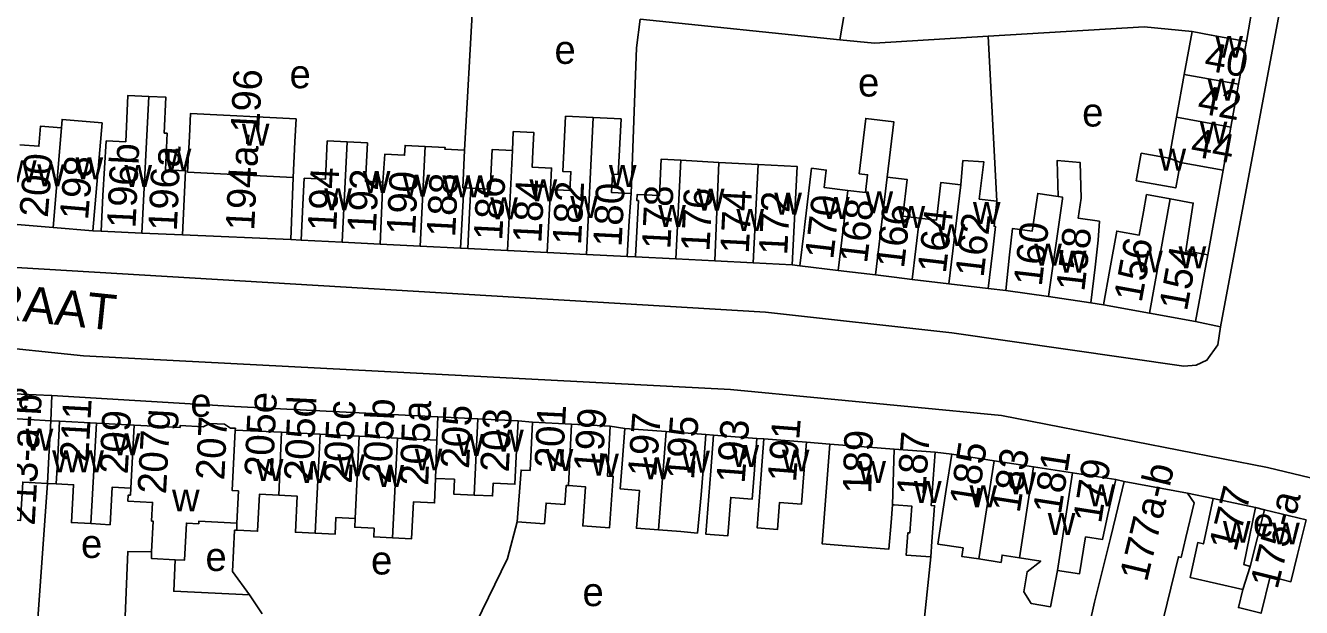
# Model space of a CAD drawing. Extents: x 157569 to 159501, y 382907 to 384670.
# Drawn here: x 158378.5 to 158557, y 383135.7 to 383217.2 of the extents above; entities that cross this region are included whole.
import ezdxf

# ---------------------------------------------------------------- set-up
doc = ezdxf.new("R2010")
doc.units = 0
for name, color, linetype in [('BLT_Basislijn', 7, 'Continuous'), ('BLT_Bebouwing', 7, 'Continuous'), ('BLT_Centroide', 7, 'Continuous'), ('BLT_Huisnummer', 7, 'Continuous'), ('BLT_Huisnummer_ tussenligend', 7, 'Continuous'), ('BLT_Huisnummer_reeks', 7, 'Continuous'), ('BLT_Onderdoorgang_en_onderverdeling', 7, 'Continuous'), ('BLT_Onderverdeling_panden', 7, 'Continuous'), ('BLT_Straatnaam', 7, 'Continuous')]:
    doc.layers.add(name, color=color, linetype=linetype)

msp = doc.modelspace()

# ---------------------------------------------------------------- linework, layer by layer
at = {"layer": 'BLT_Basislijn'}
for p, q in [((158494.57, 383228.1), (158492.39, 383215.18)), ((158550.98, 383224.75), (158549.26, 383214.95)), ((158441.03, 383220.43), (158439.9, 383199.74)), ((158492.39, 383215.18), (158464.44, 383218.06)), ((158514.36, 383192.58), (158513.12, 383215.69)), ((158415.92, 383195.91), (158415.58, 383187.21)), ((158543.84, 383185.09), (158545.99, 383196.95)), ((158387.91, 383188.45), (158389.06, 383188.4)), ((158400.44, 383187.87), (158415.58, 383187.21)), ((158415.58, 383187.21), (158417.03, 383187.16)), ((158463.81, 383184.79), (158462.66, 383184.84)), ((158485.73, 383183.68), (158486.81, 383183.53)), ((158515.6, 383180.1), (158513.12, 383180.39)), ((158529.25, 383178.1), (158527.51, 383178.38)), ((158545.62, 383175.03), (158542.14, 383175.76)), ((158382.03, 383161.87), (158382.17, 383165.41)), ((158447.38, 383161.85), (158449.4, 383161.66)), ((158460.28, 383161.11), (158462.32, 383160.8)), ((158474.72, 383159.84), (158473.63, 383159.94)), ((158480.78, 383159.38), (158481.77, 383159.32)), ((158491, 383158.6), (158487.7, 383158.86)), ((158505.73, 383157.49), (158508.04, 383157.18)), ((158380.05, 383132.21), (158381.55, 383153.1)), ((158532.17, 383153.37), (158531, 383153.63)), ((158544.6, 383150.99), (158541.02, 383151.73)), ((158550.55, 383149.72), (158551.78, 383149.4)), ((158407.45, 383140.78), (158407.72, 383146.55)), ((158407.72, 383146.55), (158408.05, 383146.54)), ((158505.11, 383142.8), (158503.88, 383130.9)), ((158407.45, 383140.78), (158409.81, 383137.51))]:
    msp.add_line(p, q, dxfattribs=at)
for points in [[(158555.85, 383237.47), (158556.46, 383236.09), (158556.55, 383234.91), (158556.23, 383231.55), (158545.62, 383175.03)], [(158135.77, 383231.67), (158137.79, 383229.1), (158140.67, 383227.08), (158144.24, 383226.07), (158171.27, 383222.4), (158308.16, 383193.45), (158320.58, 383190.57), (158326.95, 383189.46), (158362.07, 383184.81), (158374.02, 383183.51), (158481.99, 383177.07), (158508.03, 383174.16), (158540.49, 383169.52), (158542.23, 383169.64), (158543.74, 383170.33), (158545.24, 383172.5), (158545.62, 383175.03)], [(158464.44, 383218.06), (158463.94, 383214.05), (158463.22, 383193.67)], [(158492.39, 383215.18), (158497.23, 383214.73), (158513.12, 383215.69)], [(158541.66, 383216.34), (158534.94, 383217), (158513.12, 383215.69)], [(158136.23, 383207.98), (158138.34, 383210.7), (158142.33, 383213.13), (158148.56, 383213.38), (158153.24, 383212.69), (158183.67, 383207.66), (158286.08, 383185.1), (158316.24, 383179.46), (158331.59, 383176.95), (158343.62, 383175.44), (158386.57, 383170.97), (158477.11, 383166.26), (158514.99, 383162.58), (158552.21, 383155.31), (158614.72, 383140.3), (158637.24, 383136.07), (158653.85, 383134.55), (158675.54, 383133.02), (158693.44, 383133.82), (158697.11, 383133.9), (158699.66, 383132.24), (158700.59, 383130.97), (158702.07, 383127.4)], [(158371.53, 383165.87), (158382.06, 383165.41), (158382.17, 383165.41)], [(158436.17, 383162.41), (158407.73, 383163.87), (158382.17, 383165.41)], [(158439.7, 383129.86), (158445.88, 383142.61), (158447.26, 383147.72)]]:
    msp.add_lwpolyline(points, dxfattribs=at)
at = {"layer": 'BLT_Bebouwing'}
for p, q in [((158540.57, 383210.34), (158541.66, 383216.34)), ((158549.26, 383214.95), (158548.17, 383208.95)), ((158539.48, 383204.34), (158540.57, 383210.34)), ((158548.17, 383208.95), (158547.08, 383202.95)), ((158538.43, 383198.6), (158539.48, 383204.34)), ((158547.08, 383202.95), (158545.99, 383196.95)), ((158470.16, 383198.34), (158475.47, 383198.03)), ((158475.47, 383198.03), (158480.96, 383197.72)), ((158545.99, 383196.95), (158540.03, 383198.03)), ((158439.77, 383194.47), (158440.77, 383194.42)), ((158382.33, 383188.92), (158376.76, 383189.39)), ((158387.91, 383188.45), (158382.33, 383188.92)), ((158389.06, 383188.4), (158394.75, 383188.14)), ((158400.44, 383187.87), (158394.75, 383188.14)), ((158422.78, 383186.86), (158417.03, 383187.16)), ((158428.09, 383186.6), (158422.78, 383186.86)), ((158433.67, 383186.31), (158428.09, 383186.6)), ((158439.34, 383186.03), (158433.67, 383186.31)), ((158439.34, 383186.03), (158440.34, 383185.98)), ((158445.9, 383185.69), (158440.34, 383185.98)), ((158451.47, 383185.41), (158445.9, 383185.69)), ((158456.93, 383185.13), (158451.47, 383185.41)), ((158462.66, 383184.84), (158456.93, 383185.13)), ((158463.81, 383184.79), (158469.46, 383184.51)), ((158469.46, 383184.51), (158474.88, 383184.23)), ((158474.88, 383184.23), (158480.26, 383183.96)), ((158480.26, 383183.96), (158485.73, 383183.68)), ((158492.16, 383182.89), (158486.81, 383183.53)), ((158543.84, 383185.09), (158542.14, 383175.76)), ((158497.37, 383182.27), (158492.16, 383182.89)), ((158502.52, 383181.65), (158507.65, 383181.04)), ((158507.65, 383181.04), (158513.12, 383180.39)), ((158521.55, 383179.24), (158515.6, 383180.1)), ((158527.51, 383178.38), (158521.55, 383179.24)), ((158535.69, 383176.93), (158529.25, 383178.1)), ((158542.14, 383175.76), (158535.69, 383176.93)), ((158382.03, 383161.87), (158375.76, 383162.22)), ((158436.17, 383162.41), (158436.01, 383159.17)), ((158441.77, 383162.13), (158436.17, 383162.41)), ((158447.38, 383161.85), (158441.77, 383162.13)), ((158382.03, 383161.87), (158383.25, 383161.8)), ((158388.39, 383161.54), (158383.25, 383161.8)), ((158393.7, 383161.27), (158388.39, 383161.54)), ((158414.28, 383160.25), (158407.81, 383160.57)), ((158419.71, 383159.98), (158414.28, 383160.25)), ((158454.84, 383161.39), (158449.4, 383161.66)), ((158460.28, 383161.11), (158454.84, 383161.39)), ((158468.09, 383160.36), (158462.32, 383160.8)), ((158473.63, 383159.94), (158468.09, 383160.36)), ((158425.17, 383159.71), (158419.71, 383159.98)), ((158430.53, 383159.44), (158425.17, 383159.71)), ((158436.01, 383159.17), (158430.53, 383159.44)), ((158480.78, 383159.38), (158474.72, 383159.84)), ((158487.7, 383158.86), (158481.77, 383159.32)), ((158500, 383157.91), (158491, 383158.6)), ((158505.73, 383157.49), (158500, 383157.91)), ((158513.97, 383156.26), (158508.04, 383157.18)), ((158519.49, 383155.41), (158513.97, 383156.26)), ((158524.95, 383154.57), (158519.49, 383155.41)), ((158382.77, 383153.03), (158381.55, 383153.1)), ((158531, 383153.63), (158524.95, 383154.57)), ((158541.02, 383151.73), (158532.17, 383153.37)), ((158544.6, 383150.99), (158550.55, 383149.72)), ((158549.78, 383141.46), (158551.78, 383149.4)), ((158551.78, 383149.4), (158557.6, 383147.99)), ((158408.05, 383146.54), (158408.04, 383147.53)), ((158409.81, 383137.51), (158411.56, 383134.85))]:
    msp.add_line(p, q, dxfattribs=at)
for points in [[(158541.66, 383216.34), (158544.34, 383215.85), (158549.26, 383214.95)], [(158395.75, 383207.25), (158392.81, 383207.39), (158392.51, 383200.92), (158389.78, 383201.04), (158389.3, 383193.39), (158389.06, 383188.4)], [(158395.75, 383207.25), (158398.12, 383207.14), (158397.89, 383202.13), (158398.28, 383202.11), (158398.04, 383196.98), (158400.86, 383196.85), (158400.68, 383192.87), (158400.44, 383187.87)], [(158416.34, 383204.12), (158401.57, 383204.87), (158401.41, 383201.65), (158401.15, 383196.65)], [(158377.68, 383200.5), (158380.35, 383200.28), (158380.59, 383203.11), (158383.5, 383202.86)], [(158383.5, 383202.86), (158383.59, 383204.03), (158389.18, 383203.56), (158387.91, 383188.45)], [(158415.92, 383195.91), (158416.17, 383200.9), (158416.34, 383204.12)], [(158451.91, 383194.22), (158454.63, 383194.08), (158454.76, 383196.71), (158453.63, 383196.77), (158454.02, 383204.49), (158457.9, 383204.29)], [(158457.9, 383204.29), (158461.78, 383204.1), (158461.39, 383196.35), (158460.59, 383196.39), (158460.46, 383193.81), (158463.22, 383193.67)], [(158493.5, 383194.11), (158495.96, 383193.83), (158496.26, 383196.29), (158495.1, 383196.43), (158496.02, 383204.18), (158499.92, 383203.71), (158499, 383195.95)], [(158446.62, 383199.71), (158446.7, 383202.33), (158449.6, 383202.19), (158449.46, 383199.56), (158449.35, 383197.35), (158452.07, 383197.22), (158451.91, 383194.22)], [(158417.03, 383187.16), (158417.29, 383192.15), (158417.47, 383195.81), (158420.42, 383195.66), (158420.69, 383201.03), (158423.49, 383200.89)], [(158423.49, 383200.89), (158426.3, 383200.75), (158426.02, 383195.38), (158428.45, 383195.25)], [(158428.45, 383195.25), (158428.73, 383199.16), (158431.51, 383199.02), (158431.58, 383200.4), (158434.37, 383200.26)], [(158434.37, 383200.26), (158437.17, 383200.12), (158437.15, 383199.87), (158439.9, 383199.74)], [(158439.77, 383194.47), (158439.64, 383194.47), (158439.9, 383199.74)], [(158440.77, 383194.42), (158443.48, 383194.28), (158443.77, 383199.85), (158446.62, 383199.71)], [(158470.16, 383198.34), (158467.4, 383198.48), (158467.14, 383193.37), (158464.02, 383193.53), (158463.97, 383192.7), (158464.21, 383192.69), (158463.81, 383184.91), (158463.81, 383184.79)], [(158485.73, 383183.68), (158486.43, 383197.44), (158480.96, 383197.72)], [(158509.3, 383194.9), (158509.6, 383198.28), (158512.51, 383198.11), (158511.89, 383192.88), (158514.36, 383192.58)], [(158522.91, 383193.27), (158522.78, 383198.27), (158526.02, 383197.99), (158526.15, 383193.04), (158525.74, 383190.21), (158528.69, 383189.79), (158528.52, 383187.16), (158528.08, 383183.35), (158527.51, 383178.38)], [(158538.43, 383198.6), (158534.54, 383199.31), (158533.84, 383195.45), (158539.38, 383194.45), (158540.03, 383198.03)], [(158401.15, 383196.65), (158415.92, 383195.91)], [(158486.81, 383183.53), (158487.4, 383188.49), (158487.46, 383188.96), (158488.44, 383197.2), (158490.48, 383196.95), (158490.19, 383194.51), (158493.5, 383194.11)], [(158499, 383195.95), (158501.8, 383195.64), (158501.19, 383190.5), (158503.54, 383190.22)], [(158503.54, 383190.22), (158505.89, 383189.94), (158506.52, 383195.23), (158509.3, 383194.9)], [(158463.22, 383193.67), (158462.92, 383189.84), (158462.66, 383184.84)], [(158513.12, 383180.39), (158513.72, 383185.35), (158514.16, 383189.05), (158513.95, 383189.08), (158514.36, 383192.58)], [(158515.6, 383180.1), (158516.14, 383185.07), (158516.54, 383188.79), (158519.3, 383188.4), (158520.06, 383193.68), (158522.91, 383193.27)], [(158529.25, 383178.1), (158530.14, 383183.02), (158531.13, 383188.42), (158534.26, 383187.86), (158534.85, 383191.1), (158535.29, 383193.51), (158538.6, 383192.91)], [(158538.6, 383192.91), (158541.81, 383192.33), (158540.78, 383185.64), (158543.84, 383185.09)], [(158502.52, 383181.65), (158500, 383181.95), (158497.37, 383182.27)], [(158407.81, 383160.57), (158407.83, 383160.82), (158407.14, 383160.85), (158406.32, 383161.39), (158404.28, 383161.5), (158403.33, 383161.02), (158400.1, 383161.2), (158400.09, 383160.94), (158393.7, 383161.27)], [(158447.38, 383161.85), (158447.13, 383156.85), (158446.93, 383152.99), (158443.9, 383153.14), (158443.81, 383151.34), (158441.24, 383151.46)], [(158449.4, 383161.66), (158449.06, 383154.91), (158447.8, 383154.97), (158447.26, 383147.72)], [(158460.28, 383161.11), (158459.9, 383154.11), (158460.69, 383154.07), (158460.15, 383146.87), (158456.42, 383147.14), (158456.82, 383152.61), (158454.41, 383152.79)], [(158462.32, 383160.8), (158461.94, 383155.82), (158461.68, 383152.33), (158464.35, 383152.12), (158463.94, 383146.83), (158467.04, 383146.6)], [(158473.63, 383159.94), (158473.25, 383154.96), (158472.99, 383151.48), (158472.46, 383146.14), (158470.13, 383146.36), (158467.04, 383146.6)], [(158474.72, 383159.84), (158474.34, 383154.85), (158473.66, 383145.98), (158476.71, 383145.75), (158477.12, 383151.14), (158480.13, 383150.91), (158480.4, 383154.39), (158480.78, 383159.38)], [(158481.77, 383159.32), (158481.39, 383154.33), (158480.83, 383146.86), (158483.66, 383146.64), (158483.95, 383150.44), (158487.04, 383150.2), (158487.32, 383153.88), (158487.7, 383158.86)], [(158491, 383158.6), (158489.93, 383144.62), (158493.27, 383144.36), (158499.23, 383143.88), (158499.57, 383147.64), (158499.76, 383150.11)], [(158505.11, 383142.8), (158505.27, 383144.98), (158505.65, 383149.97), (158505.17, 383150), (158505.73, 383157.49)], [(158508.04, 383157.18), (158507.27, 383152.24), (158506.1, 383144.61), (158509.63, 383144.06), (158509.45, 383142.89), (158511.85, 383142.52)], [(158381.55, 383153.1), (158378.09, 383153.29), (158377.79, 383147.92), (158375.02, 383148.04)], [(158382.77, 383153.03), (158385.21, 383152.9), (158384.91, 383147.61), (158387.62, 383147.47)], [(158435.84, 383153.8), (158435.69, 383150.37), (158432.74, 383150.51), (158432.49, 383145.34), (158429.83, 383145.47)], [(158441.24, 383151.46), (158438.37, 383151.61), (158438.47, 383153.67), (158435.84, 383153.8)], [(158531, 383153.63), (158529.89, 383148.76), (158529.11, 383145.24), (158526.76, 383145.6), (158525.89, 383140.43), (158522.84, 383140.9)], [(158532.17, 383153.37), (158531, 383148.51), (158530.25, 383145.42), (158528, 383136.47), (158524.26, 383119.84)], [(158393.22, 383152.44), (158390.61, 383152.59), (158390.32, 383147.32), (158387.62, 383147.47)], [(158396.12, 383143.52), (158396.34, 383147.81), (158396.12, 383147.82), (158396.26, 383150.44), (158392.8, 383150.63), (158392.84, 383151.47), (158393.16, 383151.46), (158393.22, 383152.44)], [(158413.9, 383151.44), (158411.19, 383151.57), (158410.93, 383146.39), (158408.05, 383146.54)], [(158419.01, 383146.11), (158416.24, 383146.25), (158416.5, 383151.31), (158413.9, 383151.44)], [(158454.41, 383152.79), (158454.12, 383152.81), (158453.92, 383150.15), (158451.29, 383150.34), (158451.07, 383147.44), (158447.26, 383147.72)], [(158541.02, 383151.73), (158541.95, 383150.38), (158540.79, 383145.52), (158540.12, 383142.74), (158539.75, 383142.83), (158536.57, 383129.86), (158533.8, 383130.37), (158532.5, 383124.72)], [(158505.11, 383142.8), (158501.66, 383143.06), (158501.9, 383146.2), (158502.19, 383146.18), (158502.47, 383149.9), (158500, 383150.09), (158499.76, 383150.11)], [(158548.75, 383138.24), (158541.4, 383139.92), (158542.45, 383144.81), (158543.24, 383144.64), (158544.6, 383150.99)], [(158550.55, 383149.72), (158548.91, 383141.73), (158549.78, 383141.46)], [(158408.04, 383147.53), (158402.74, 383147.82), (158402.72, 383147.46), (158400.98, 383147.55), (158400.71, 383142.35), (158399.43, 383142.42)], [(158424.6, 383148.19), (158421.9, 383148.33), (158421.78, 383145.97), (158419.01, 383146.11)], [(158429.83, 383145.47), (158427.18, 383145.61), (158427.24, 383146.82), (158424.54, 383146.95), (158424.6, 383148.19)], [(158557.6, 383147.99), (158556.42, 383143.13), (158555.49, 383139.33), (158552.56, 383140.05), (158551.32, 383134.93), (158548.13, 383135.71), (158548.75, 383138.24)], [(158410.22, 383128.35), (158387.55, 383132.08), (158387.52, 383133.96), (158392.41, 383134.48), (158392.8, 383143.59), (158396.12, 383143.52)], [(158399.43, 383142.42), (158399.22, 383138.01), (158409.81, 383137.51)], [(158517.51, 383142.69), (158515.09, 383143.06), (158514.93, 383142.04), (158511.85, 383142.52)], [(158522.84, 383140.9), (158521.87, 383135.84), (158519.15, 383136.28), (158518.13, 383137.92), (158518.57, 383140.73), (158520.5, 383142.23), (158517.51, 383142.69)]]:
    msp.add_lwpolyline(points, dxfattribs=at)
at = {"layer": 'BLT_Onderdoorgang_en_onderverdeling'}
for points in [[(158439.77, 383194.47), (158439.6, 383191.02), (158439.34, 383186.03)], [(158440.34, 383185.98), (158440.6, 383190.97), (158440.77, 383194.42)], [(158382.03, 383161.87), (158381.76, 383156.88), (158381.55, 383153.1)], [(158383.25, 383161.8), (158382.98, 383156.81), (158382.77, 383153.03)]]:
    msp.add_lwpolyline(points, dxfattribs=at)
at = {"layer": 'BLT_Onderverdeling_panden'}
for p, q in [((158548.17, 383208.95), (158540.57, 383210.34)), ((158394.75, 383188.14), (158395.75, 383207.25)), ((158457.9, 383204.29), (158456.93, 383185.13)), ((158547.08, 383202.95), (158539.48, 383204.34)), ((158382.33, 383188.92), (158383.5, 383202.86)), ((158423.49, 383200.89), (158422.78, 383186.86)), ((158434.37, 383200.26), (158433.67, 383186.31)), ((158446.62, 383199.71), (158445.9, 383185.69)), ((158470.16, 383198.34), (158469.46, 383184.51)), ((158475.47, 383198.03), (158474.88, 383184.23)), ((158480.96, 383197.72), (158480.26, 383183.96)), ((158538.43, 383198.6), (158540.03, 383198.03)), ((158499, 383195.95), (158497.37, 383182.27)), ((158428.45, 383195.25), (158428.09, 383186.6)), ((158451.91, 383194.22), (158451.47, 383185.41)), ((158493.5, 383194.11), (158492.16, 383182.89)), ((158535.69, 383176.93), (158538.6, 383192.91)), ((158503.54, 383190.22), (158502.52, 383181.65)), ((158441.77, 383162.13), (158441.24, 383151.46)), ((158387.62, 383147.47), (158388.39, 383161.54)), ((158393.22, 383152.44), (158393.7, 383161.27)), ((158413.9, 383151.44), (158414.28, 383160.25)), ((158454.41, 383152.79), (158454.84, 383161.39)), ((158467.04, 383146.6), (158468.09, 383160.36)), ((158419.01, 383146.11), (158419.71, 383159.98)), ((158424.6, 383148.19), (158425.17, 383159.71)), ((158429.83, 383145.47), (158430.53, 383159.44)), ((158436.01, 383159.17), (158435.84, 383153.8)), ((158499.76, 383150.11), (158500, 383157.91)), ((158511.85, 383142.52), (158513.97, 383156.26)), ((158517.51, 383142.69), (158519.49, 383155.41)), ((158522.84, 383140.9), (158524.95, 383154.57)), ((158549.78, 383141.46), (158548.75, 383138.24))]:
    msp.add_line(p, q, dxfattribs=at)
for points in [[(158509.3, 383194.9), (158509.3, 383194.9), (158507.65, 383181.04)], [(158521.55, 383179.24), (158523.52, 383192.94), (158523.51, 383193.18), (158522.91, 383193.27)], [(158408.04, 383147.53), (158408.27, 383152.04), (158407.39, 383152.09), (158407.81, 383160.57)], [(158396.12, 383143.52), (158396.08, 383142.59), (158399.43, 383142.42)]]:
    msp.add_lwpolyline(points, dxfattribs=at)

# ---------------------------------------------------------------- texts
at = {"layer": 'BLT_Centroide'}
for s, p in [('w', (158544.91, 383212.66)), ('e', (158452.47, 383211.81)), ('e', (158415.41, 383208.4)), ('e', (158494.93, 383207.24)), ('w', (158543.82, 383206.66)), ('e', (158526.28, 383203.04)), ('w', (158408.74, 383200.38)), ('w', (158542.73, 383200.66)), ('w', (158397.81, 383196.88)), ('w', (158536.96, 383196.88)), ('w', (158376.17, 383195.25)), ('w', (158380.12, 383194.69)), ('w', (158385.48, 383195.67)), ('w', (158392.31, 383194.59)), ('w', (158460.08, 383194.58)), ('w', (158425.66, 383193.75)), ('w', (158431.23, 383193.25)), ('w', (158436.78, 383193.14)), ('w', (158440.14, 383193.14)), ('w', (158420.27, 383191.33)), ('w', (158448.98, 383192.56)), ('w', (158472.39, 383191.28)), ('w', (158443.48, 383190.05)), ('w', (158454.69, 383190.23)), ('w', (158483.22, 383190.7)), ('w', (158489.89, 383190.09)), ('w', (158495.97, 383190.88)), ('w', (158511, 383189.41)), ('w', (158466.98, 383189)), ('w', (158477.92, 383188.42)), ('w', (158500.45, 383188.84)), ('w', (158506.06, 383186.3)), ('w', (158519.58, 383183.57)), ('w', (158523.03, 383182.6)), ('w', (158533.7, 383182.62)), ('w', (158539.77, 383183.2)), ('e', (158376.14, 383163.24)), ('e', (158401.54, 383162.43)), ('w', (158378.5, 383157.67)), ('w', (158444.31, 383157.56)), ('w', (158390.66, 383157.02)), ('w', (158438.75, 383156.94)), ('w', (158477.22, 383155.39)), ('w', (158382.21, 383154.64)), ('w', (158385.58, 383154.64)), ('w', (158422.09, 383154.09)), ('w', (158432.92, 383154.91)), ('w', (158451.23, 383154.83)), ('w', (158457.61, 383154.2)), ('w', (158464.88, 383153.69)), ('w', (158470.33, 383154.59)), ('w', (158484.27, 383154.77)), ('w', (158410.69, 383153.42)), ('w', (158416.78, 383153.17)), ('w', (158427.56, 383152.59)), ('w', (158494.97, 383153.14)), ('w', (158502.75, 383150.34)), ('w', (158515.97, 383151.59)), ('w', (158527.06, 383149.91)), ('w', (158398.97, 383149.17)), ('w', (158510.52, 383149.77)), ('w', (158521.47, 383145.88)), ('w', (158545.97, 383144.78)), ('e', (158550.17, 383145.65)), ('w', (158552.86, 383144.55)), ('e', (158386.24, 383142.66)), ('e', (158403.65, 383140.84)), ('e', (158426.81, 383140.35)), ('e', (158456.39, 383135.92))]:
    msp.add_text(s, height=4, dxfattribs=at).set_placement(p)
at = {"layer": 'BLT_Huisnummer'}
for s, rotation, p in [('40', 349.6759, (158543.2, 383210.97)), ('44', 349.6759, (158541.3, 383198.96)), ('196b', 87.3457, (158393.86, 383188.74)), ('196a', 87.3407, (158399.64, 383188.35)), ('198', 85.2164, (158387.22, 383189.88)), ('194', 87.0927, (158421.93, 383188.32)), ('188', 87.0927, (158438.57, 383187.51)), ('186', 87.0927, (158445.15, 383187.04)), ('180', 87.0913, (158461.85, 383186.14)), ('178', 87.0913, (158468.67, 383185.81)), ('172', 87.0913, (158485.02, 383184.98)), ('170', 83.3852, (158491.45, 383184.36)), ('166', 83.3852, (158501.35, 383183.1)), ('162', 83.3852, (158512.48, 383181.84)), ('160', 83.3852, (158520.62, 383180.58)), ('158', 83.3852, (158526.58, 383179.85)), ('156', 79.6836, (158534.59, 383178.29)), ('154', 79.6854, (158540.93, 383177.09)), ('205e', 87.1476, (158413.07, 383153.92)), ('211', 86.8441, (158387.25, 383155.98)), ('205d', 87.1444, (158418.61, 383153.34)), ('205c', 87.1569, (158424.1, 383153.02)), ('205b', 87.1437, (158429.58, 383153.02)), ('205a', 87.9841, (158434.81, 383152.72)), ('205', 87.145, (158440.51, 383155.09)), ('201', 87.1545, (158453.66, 383155.14)), ('209', 86.8471, (158392.77, 383154.33)), ('199', 85.6347, (158459.11, 383154.6)), ('197', 85.6347, (158466.69, 383153.92)), ('195', 85.6408, (158471.98, 383153.54)), ('193', 85.6408, (158479.06, 383153.02)), ('191', 85.6451, (158486.25, 383153.19)), ('189', 88.2472, (158496.77, 383151.6)), ('187', 85.7154, (158504.32, 383151.28)), ('185', 81.2116, (158511.63, 383149.75)), ('179', 81.223, (158528.93, 383147.38)), ('177', 75.8739, (158547.81, 383143.41))]:
    msp.add_text(s, height=4, rotation=rotation, dxfattribs=at).set_placement(p)
at = {"layer": 'BLT_Huisnummer_ tussenligend'}
for s, rotation, p in [('42', 349.6759, (158542.26, 383204.97)), ('200', 85.2164, (158381.58, 383190.22)), ('192', 87.0927, (158427.47, 383188.09)), ('190', 87.0927, (158432.97, 383187.79)), ('184', 87.0927, (158450.63, 383186.67)), ('182', 87.0927, (158456.18, 383186.4)), ('176', 87.0913, (158474.14, 383185.48)), ('174', 87.0913, (158479.64, 383185.19)), ('168', 83.3852, (158496.19, 383183.8)), ('164', 83.3852, (158507.2, 383182.4)), ('203', 87.1545, (158446.07, 383154.59)), ('183', 81.223, (158517.53, 383148.86)), ('181', 81.223, (158523.3, 383148.62))]:
    msp.add_text(s, height=4, rotation=rotation, dxfattribs=at).set_placement(p)
at = {"layer": 'BLT_Huisnummer_reeks'}
for s, rotation, p in [('194a-196', 87.0998, (158410.46, 383188.41)), ('213-a-b', 86.8382, (158379.76, 383147.15)), ('207g', 86.8458, (158398.13, 383151.54)), ('207', 87.1476, (158406.28, 383153.48)), ('177a-b', 76.6047, (158535.34, 383139.19)), ('175-a', 76.0638, (158553.59, 383138.15))]:
    msp.add_text(s, height=4, rotation=rotation, dxfattribs=at).set_placement(p)
at = {"layer": 'BLT_Straatnaam'}
msp.add_text('ZEELSTERSTRAAT', height=5, rotation=354.0866, dxfattribs=at).set_placement((158330.3, 383180.74))

doc.saveas('drawing.dxf')
